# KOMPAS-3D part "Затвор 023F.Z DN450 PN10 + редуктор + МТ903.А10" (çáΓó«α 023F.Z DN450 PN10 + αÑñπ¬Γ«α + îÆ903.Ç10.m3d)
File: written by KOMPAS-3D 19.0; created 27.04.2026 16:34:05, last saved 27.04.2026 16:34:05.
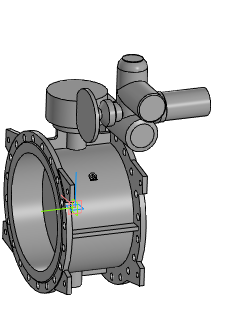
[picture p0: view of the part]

Document properties: Полное имя файла: ..\..\Затвор 023F.Z DN400-DN1600 + редуктор + МТ903\Затвор 023F.Z DN450 PN10 + редуктор + МТ903.А10.a3d

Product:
- Part/product: Затвор 023F.Z DN450 PN10 + редуктор + МТ903.А10
    Масса: 300.376

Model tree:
1. Операция без истории:1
